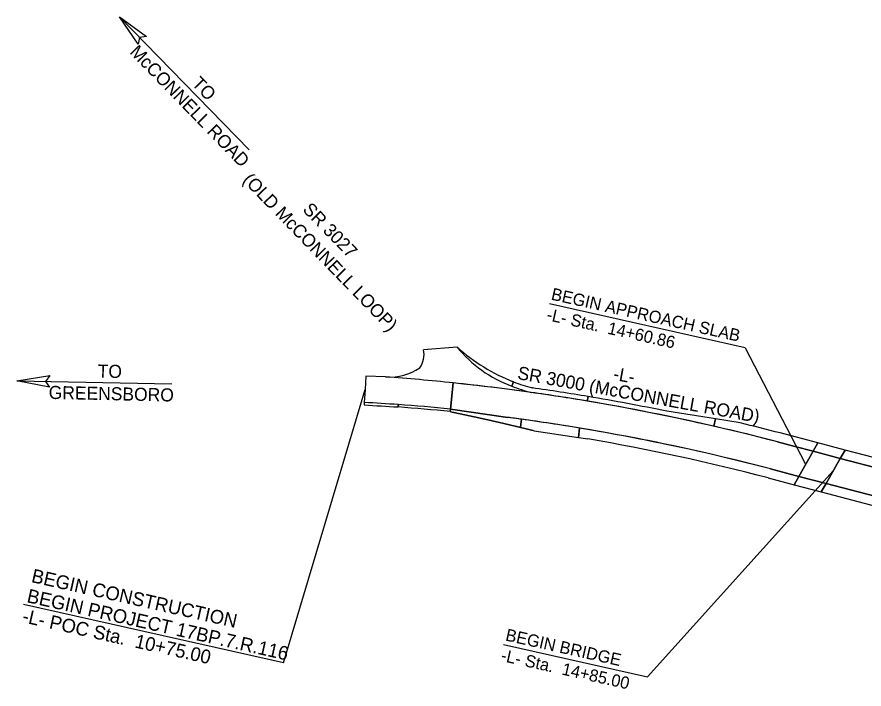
# Model space of a CAD drawing. Extents: x 1784499 to 1786147, y 841097 to 842538.
# Drawn here: x 1784737 to 1785466, y 841280 to 841859 of the extents above; entities that cross this region are included whole.
import ezdxf

# ---------------------------------------------------------------- set-up
doc = ezdxf.new("R2010")
doc.units = 0
for name, color, linetype in [('Exist Roads EOP Text', 7, 'Continuous'), ('Prop DSN Text', 7, 'Continuous'), ('Prop Horizontal Alignment Station Label', 7, 'Continuous'), ('Prop Leader Line Medium', 7, 'Continuous'), ('Prop Shade Light', 7, 'Continuous'), ('Prop Terminator CELL', 7, 'Continuous')]:
    doc.layers.add(name, color=color, linetype=linetype)

msp = doc.modelspace()

# ---------------------------------------------------------------- linework, layer by layer
at = {"layer": 'Prop DSN Text'}
for p, q in [((1785364.2, 841574.14), (1785195.45, 841611.98)), ((1785364.2, 841574.14), (1785415.69, 841474.44)), ((1785279.88, 841290.82), (1785439.87, 841468.1)), ((1785155.81, 841318.64), (1785279.88, 841290.82))]:
    msp.add_line(p, q, dxfattribs=at)
at = {"layer": 'Prop Horizontal Alignment Station Label'}
for q in [(1785036.69, 841538.18), (1784742.41, 841353.09)]:
    msp.add_line((1784966.33, 841302.87), q, dxfattribs=at)
at = {"layer": 'Prop Leader Line Medium'}
for p, q in [((1784825.08, 841858.92), (1784936.86, 841744.54)), ((1784736.77, 841545.72), (1784870.17, 841543.05))]:
    msp.add_line(p, q, dxfattribs=at)
at = {"layer": 'Prop Shade Light'}
for p, q in [((1785115.87, 841574.68), (1785087, 841572.35)), ((1785054.29, 841549.01), (1785037.41, 841549.61)), ((1785112.66, 841543.87), (1785110.33, 841521.41)), ((1785110.33, 841521.41), (1785112.66, 841543.87)), ((1785163.05, 841541.1), (1785164.56, 841544.78)), ((1785227.93, 841528.23), (1785228.81, 841532.14)), ((1785228.81, 841532.14), (1785227.93, 841528.23)), ((1785035.99, 841527.06), (1785035.85, 841524.92)), ((1785065.19, 841525.2), (1785065.3, 841525.2)), ((1785110.33, 841521.41), (1785110.09, 841519.14)), ((1785110.33, 841521.41), (1785159.51, 841514.19)), ((1785159.51, 841514.19), (1785110.33, 841521.41)), ((1785338.37, 841512.82), (1785296.57, 841519.48)), ((1785170.53, 841505.64), (1785171.42, 841512.59)), ((1785171.42, 841512.59), (1785170.53, 841505.64)), ((1785336.97, 841506.58), (1785338.37, 841512.82)), ((1785338.37, 841512.82), (1785336.97, 841506.58)), ((1785359.82, 841509.41), (1785338.37, 841512.82)), ((1785182.33, 841502.75), (1785220.63, 841496.88)), ((1785220.63, 841496.88), (1785221.32, 841505)), ((1785221.32, 841505), (1785220.63, 841496.88)), ((1785426.78, 841492.21), (1785394.08, 841500.78)), ((1785220.63, 841496.88), (1785228.55, 841495.67)), ((1785426.78, 841492.21), (1785422.67, 841485.01)), ((1785422.67, 841485.01), (1785426.78, 841492.21)), ((1785450.13, 841486.09), (1785426.78, 841492.21)), ((1785410.37, 841463.43), (1785422.67, 841485.01)), ((1785422.67, 841485.01), (1785410.37, 841463.43)), ((1785446.03, 841478.89), (1785422.67, 841485.01)), ((1785422.67, 841485.01), (1785446.03, 841478.89)), ((1785446.03, 841478.89), (1785450.13, 841486.09)), ((1785450.13, 841486.09), (1785446.03, 841478.89)), ((1785503.33, 841472.15), (1785450.13, 841486.09)), ((1785446.03, 841478.89), (1785433.72, 841457.31)), ((1785433.72, 841457.31), (1785446.03, 841478.89)), ((1785499.23, 841464.95), (1785446.03, 841478.89)), ((1785446.03, 841478.89), (1785499.23, 841464.95)), ((1785385.97, 841469.82), (1785410.37, 841463.43)), ((1785410.37, 841463.43), (1785385.97, 841469.82)), ((1785383.94, 841462.08), (1785406.27, 841456.23)), ((1785410.37, 841463.43), (1785406.27, 841456.23)), ((1785406.27, 841456.23), (1785410.37, 841463.43)), ((1785410.37, 841463.43), (1785433.72, 841457.31)), ((1785433.72, 841457.31), (1785410.37, 841463.43)), ((1785433.72, 841457.31), (1785429.62, 841450.11)), ((1785433.72, 841457.31), (1785486.92, 841443.36)), ((1785486.92, 841443.36), (1785433.72, 841457.31)), ((1785429.62, 841450.11), (1785482.82, 841436.17))]:
    msp.add_line(p, q, dxfattribs=at)
for points in [[(1785037.41, 841549.61), (1785036.69, 841538.18), (1785035.99, 841527.06)], [(1785164.57, 841544.81), (1785164.57, 841544.81), (1785164.57, 841544.8), (1785164.56, 841544.78), (1785163.05, 841541.1)], [(1785164.56, 841544.78), (1785163.59, 841545.18), (1785164.44, 841544.86), (1785164.52, 841544.83)], [(1785180.78, 841539.53), (1785180.33, 841539.62)], [(1785065.08, 841523.15), (1785065.19, 841525.2)], [(1785065.3, 841525.19), (1785065.08, 841523.15)], [(1785065.3, 841525.2), (1785065.3, 841525.19)], [(1785110.09, 841519.14), (1785110.17, 841521.41), (1785110.33, 841521.41)], [(1785422.67, 841485.01), (1785406.88, 841489.15), (1785392.05, 841493.04)], [(1785392.05, 841493.04), (1785406.88, 841489.15), (1785422.67, 841485.01)], [(1785406.27, 841456.23), (1785429.62, 841450.11), (1785433.72, 841457.31)]]:
    msp.add_lwpolyline(points, dxfattribs=at)
for centre, radius, start, end in [((1785224.23, 841696.69), 163.18, 228.38859, 248.53293), ((1785201.46, 841645.01), 110.78, 219.40926, 249.71325), ((1785201.46, 841645.01), 110.78, 219.40926, 249.71325), ((1784920.03, 839691.86), 1862, 84.06172, 85.86495), ((1784920.03, 839691.86), 1862, 84.06172, 85.86495), ((1784920.03, 839691.86), 1862, 75.31501, 84.06172), ((1784920.03, 839691.86), 1862, 81.98136, 84.06172), ((1785217.06, 841678.46), 143.59, 248.55527, 255.2705), ((1785217.06, 841678.46), 147.59, 248.53293, 255.36212), ((1785217.06, 841678.46), 147.59, 248.53293, 255.36212), ((1784920.03, 839691.86), 1862, 80.48165, 81.98136), ((1784920.03, 839691.86), 1866, 81.97421, 81.98136), ((1784920.03, 839691.86), 1866, 80.47495, 81.97421), ((1785217.06, 841678.46), 143.59, 255.2705, 255.36212), ((1784920.03, 839691.86), 1862, 77.06053, 80.48165), ((1784920.03, 839691.86), 1866, 78.35834, 80.47495), ((1784971.16, 840140.52), 1387.87, 86.11059, 86.11535), ((1784971.16, 840140.52), 1387.87, 86.11059, 86.11535), ((1784971.16, 840140.52), 1387.87, 84.2515, 86.11059), ((1784971.16, 840140.52), 1387.87, 84.2515, 86.11059), ((1784920.03, 839691.86), 1838, 75.31501, 82.51319), ((1784920.03, 839691.86), 1838, 82.13878, 82.51319), ((1784920.03, 839691.86), 1838, 80.56518, 82.13878), ((1784920.03, 839691.86), 1862, 75.31501, 77.06053), ((1784920.03, 839691.86), 1870, 75.31501, 76.39761), ((1784920.03, 839691.86), 1838, 75.31501, 80.56518), ((1784920.03, 839691.86), 1830, 75.31501, 80.29419)]:
    msp.add_arc(centre, radius, start, end, dxfattribs=at)
for centre, major_axis, ratio, start_param, end_param in [((1785068.52, 841568.21), (8.59, 16.9), 0.998809, 4.544918, 5.402332), ((1785057.9, 841594.39), (38.46, 24.32), 0.999812, 4.080453, 4.752096), ((1785106.8, 843282.29), (613.02, -1622.11), 0.999956, 5.89156, 5.891859), ((1785269.39, 845347.74), (4154.31, -331.76), 0.918971, 4.729551, 4.736578), ((1784840.63, 838265.32), (-3298.97, 29.38), 0.990423, 4.653056, 4.661961), ((1784840.63, 838265.32), (-3298.97, 29.38), 0.990423, 4.653056, 4.661961), ((1784953.6, 840018.63), (-1503.92, -126.32), 0.999609, 4.524746, 4.554691)]:
    msp.add_ellipse(centre, major_axis=major_axis, ratio=ratio, start_param=start_param, end_param=end_param, dxfattribs=at)
for points in [[(1785110.09, 841519.14), (1785110.42, 841519.07), (1785110.75, 841519), (1785111.07, 841518.94), (1785111.4, 841518.87), (1785111.73, 841518.8), (1785112.06, 841518.73), (1785112.38, 841518.66), (1785112.71, 841518.6), (1785113.04, 841518.53), (1785113.37, 841518.46), (1785113.69, 841518.39), (1785114.02, 841518.33), (1785114.35, 841518.26), (1785114.67, 841518.19), (1785115, 841518.12), (1785115.33, 841518.05), (1785115.66, 841517.98), (1785115.98, 841517.92), (1785116.31, 841517.85), (1785116.64, 841517.78), (1785116.97, 841517.71), (1785117.29, 841517.64), (1785117.62, 841517.57), (1785117.95, 841517.5), (1785118.27, 841517.44), (1785118.6, 841517.37), (1785118.93, 841517.3), (1785119.25, 841517.23), (1785119.58, 841517.16), (1785119.91, 841517.09), (1785120.24, 841517.02), (1785120.56, 841516.95), (1785120.89, 841516.88), (1785121.22, 841516.81), (1785121.54, 841516.75), (1785121.87, 841516.68), (1785122.2, 841516.61), (1785122.52, 841516.54), (1785122.85, 841516.47), (1785123.18, 841516.4), (1785123.5, 841516.33), (1785123.83, 841516.26), (1785124.16, 841516.19), (1785124.48, 841516.12), (1785124.81, 841516.05), (1785125.14, 841515.98), (1785125.46, 841515.91), (1785125.79, 841515.84), (1785126.12, 841515.77), (1785126.44, 841515.7), (1785126.77, 841515.63), (1785127.1, 841515.56), (1785127.42, 841515.49), (1785127.75, 841515.42), (1785128.08, 841515.35), (1785128.4, 841515.28), (1785128.73, 841515.2), (1785129.06, 841515.13), (1785129.38, 841515.06), (1785129.71, 841514.99), (1785130.04, 841514.92), (1785130.36, 841514.85), (1785130.69, 841514.78), (1785131.01, 841514.71), (1785131.34, 841514.64), (1785131.67, 841514.57), (1785131.99, 841514.5), (1785132.32, 841514.42), (1785132.65, 841514.35), (1785132.97, 841514.28), (1785133.3, 841514.21), (1785133.62, 841514.14), (1785133.83, 841514.09), (1785134.04, 841514.05), (1785134.24, 841514)], [(1785134.24, 841514), (1785134.36, 841513.98), (1785134.48, 841513.95), (1785134.6, 841513.92), (1785134.93, 841513.85), (1785135.25, 841513.78), (1785135.58, 841513.71), (1785135.91, 841513.64), (1785136.23, 841513.56), (1785136.56, 841513.49), (1785136.89, 841513.42), (1785137.21, 841513.35), (1785137.54, 841513.28), (1785137.86, 841513.2), (1785138.19, 841513.13), (1785138.51, 841513.06), (1785138.84, 841512.99), (1785139.17, 841512.91), (1785139.49, 841512.84), (1785139.82, 841512.77), (1785140.14, 841512.7), (1785140.47, 841512.62), (1785140.8, 841512.55), (1785141.12, 841512.48), (1785141.45, 841512.4), (1785141.77, 841512.33), (1785142.1, 841512.26), (1785142.42, 841512.19), (1785142.75, 841512.11), (1785143.08, 841512.04), (1785143.4, 841511.97), (1785143.73, 841511.89), (1785144.05, 841511.82), (1785144.38, 841511.75), (1785144.7, 841511.67), (1785145.03, 841511.6), (1785145.35, 841511.52), (1785145.68, 841511.45), (1785146.01, 841511.38), (1785146.33, 841511.3), (1785146.66, 841511.23), (1785146.98, 841511.16), (1785147.31, 841511.08), (1785147.63, 841511.01), (1785147.96, 841510.93), (1785148.28, 841510.86), (1785148.61, 841510.79), (1785148.93, 841510.71), (1785149.26, 841510.64), (1785149.58, 841510.56), (1785149.91, 841510.49), (1785150.23, 841510.41), (1785150.56, 841510.34), (1785150.88, 841510.26), (1785151.21, 841510.19), (1785151.53, 841510.12), (1785151.86, 841510.04), (1785152.19, 841509.97), (1785152.51, 841509.89), (1785152.84, 841509.82), (1785153.16, 841509.74), (1785153.49, 841509.67), (1785153.81, 841509.59), (1785154.14, 841509.52), (1785154.46, 841509.44), (1785154.79, 841509.36), (1785155.11, 841509.29), (1785155.43, 841509.21), (1785155.76, 841509.14), (1785156.08, 841509.06), (1785156.41, 841508.99), (1785156.73, 841508.91), (1785157.06, 841508.84), (1785157.38, 841508.76), (1785157.71, 841508.68), (1785158.03, 841508.61), (1785158.13, 841508.59), (1785158.23, 841508.56), (1785158.33, 841508.54)], [(1785158.33, 841508.54), (1785158.55, 841508.49), (1785158.78, 841508.43), (1785159.01, 841508.38), (1785159.33, 841508.3), (1785159.66, 841508.23), (1785159.98, 841508.15), (1785160.31, 841508.08), (1785160.63, 841508), (1785160.96, 841507.92), (1785161.28, 841507.85), (1785161.6, 841507.77), (1785161.93, 841507.69), (1785162.25, 841507.62), (1785162.58, 841507.54), (1785162.9, 841507.46), (1785163.23, 841507.39), (1785163.55, 841507.31), (1785163.88, 841507.23), (1785164.2, 841507.16), (1785164.52, 841507.08), (1785164.85, 841507), (1785165.17, 841506.92), (1785165.5, 841506.85), (1785165.82, 841506.77), (1785166.15, 841506.69), (1785166.47, 841506.62), (1785166.79, 841506.54), (1785167.12, 841506.46), (1785167.44, 841506.38), (1785167.77, 841506.31), (1785168.09, 841506.23), (1785168.41, 841506.15), (1785168.74, 841506.07), (1785169.06, 841505.99), (1785169.39, 841505.92), (1785169.71, 841505.84), (1785169.98, 841505.77), (1785170.25, 841505.71), (1785170.53, 841505.64)], [(1785170.53, 841505.64), (1785170.58, 841505.63), (1785170.63, 841505.62), (1785170.68, 841505.6), (1785171.01, 841505.53), (1785171.33, 841505.45), (1785171.65, 841505.37), (1785171.98, 841505.29), (1785172.3, 841505.21), (1785172.63, 841505.13), (1785172.95, 841505.06), (1785173.27, 841504.98), (1785173.6, 841504.9), (1785173.92, 841504.82), (1785174.24, 841504.74), (1785174.57, 841504.66), (1785174.89, 841504.58), (1785175.22, 841504.5), (1785175.54, 841504.43), (1785175.86, 841504.35), (1785176.19, 841504.27), (1785176.51, 841504.19), (1785176.83, 841504.11), (1785177.16, 841504.03), (1785177.48, 841503.95), (1785177.8, 841503.87), (1785178.13, 841503.79), (1785178.45, 841503.71), (1785178.77, 841503.63), (1785179.1, 841503.55), (1785179.42, 841503.47), (1785179.75, 841503.39), (1785180.07, 841503.31), (1785180.39, 841503.23), (1785181.04, 841503.07), (1785181.69, 841502.91), (1785182.33, 841502.75)]]:
    msp.add_open_spline(points, degree=3, dxfattribs=at)
at = {"layer": 'Prop Terminator CELL'}
for points in [[(1784841.28, 841835.42), (1784825.08, 841858.92), (1784848.43, 841842.19), (1784842.34, 841841.26)], [(1784764.79, 841540.31), (1784736.77, 841545.72), (1784765.14, 841550.15), (1784761.45, 841545.22)]]:
    msp.add_lwpolyline(points, close=True, dxfattribs=at)

# ---------------------------------------------------------------- texts
at = {"layer": 'Exist Roads EOP Text'}
for s, rotation, p in [('McCONNELL ROAD', 314.25271, (1784833.25, 841828.04)), ('TO', 314.25271, (1784886.63, 841800.89)), ('(OLD McCONNELL LOOP)', 314.17475, (1784930.57, 841717.91)), ('SR 3027 ', 314.17475, (1784982.21, 841692.44)), ('TO ', 358.76624, (1784806.22, 841548.52)), ('SR 3000 (McCONNELL ROAD)', 349.66264, (1785167.33, 841547.29)), ('-L-', 349.66264, (1785249.8, 841546.58)), ('GREENSBORO', 358.76624, (1784764, 841530.14))]:
    msp.add_text(s, height=11.25, rotation=rotation, dxfattribs=at).set_placement(p)
at = {"layer": 'Prop DSN Text'}
for s, p in [('BEGIN APPROACH SLAB', (1785196.3, 841615.63)), ('-L- Sta.  14+60.86', (1785192.36, 841598.07)), ('BEGIN BRIDGE', (1785156.96, 841322.22)), ('-L- Sta.  14+85.00', (1785153.02, 841304.66))]:
    msp.add_text(s, height=10.5, rotation=347.3599, dxfattribs=at).set_placement(p)
at = {"layer": 'Prop Horizontal Alignment Station Label'}
for s, p in [('BEGIN CONSTRUCTION', (1784748.54, 841372.49)), ('BEGIN PROJECT 17BP.7.R.116', (1784744.66, 841355.2)), ('-L- POC Sta.  10+75.00', (1784740.78, 841337.91))]:
    msp.add_text(s, height=11.8125, rotation=347.3599, dxfattribs=at).set_placement(p)

doc.saveas('drawing.dxf')
